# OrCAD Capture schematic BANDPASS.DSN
size A; title: Demo; rev: A; company: EMA Design Automation; note: EMA-12345678; note: 225 Tech Park Dr; note: Rochester, NY, 14623
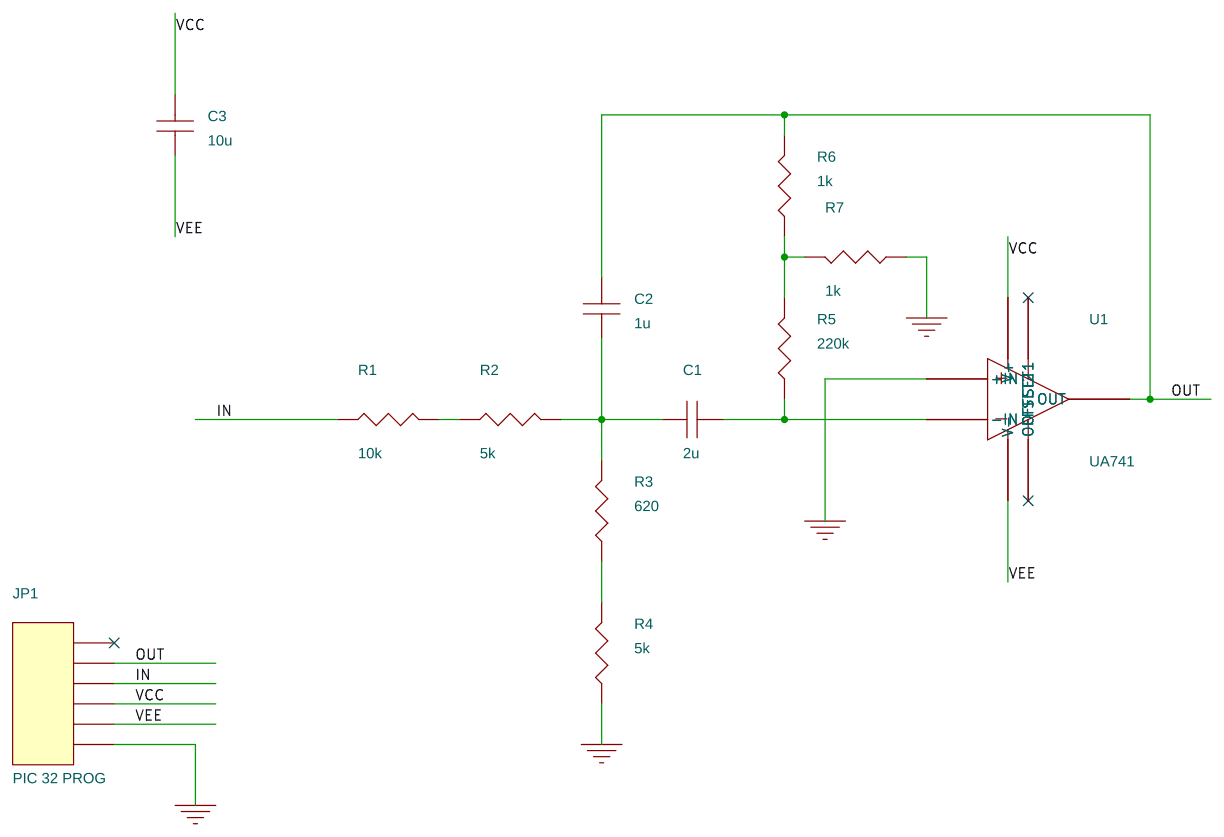
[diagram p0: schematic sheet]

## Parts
C1  2u  [0402-CAP]
C2  1u  [0402-CAP]
C3  10u  [0402-CAP]
JP1  PIC 32 PROG  [1x06_lock]
R1  10k  [0402-RES]
R2  5k  [0402-RES]
R3  620  [0402-RES]
R4  5k  [0402-RES]
R5  220k  [0402-RES]
R6  1k  [0402-RES]
R7  1k  [0402-RES]
U1  UA741  [SOIC8]

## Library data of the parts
C1-C3 = CAP_NP
JP1 = M06_LOCK: Manufacturer: TE Connectivity; Manufacturer_Part_Number: 640456-6; Part Number: A1923-ND; Vendor: DigiKey
R1-R7 = RESISTOR
U1 = UA741_1

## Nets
GND: JP1.1 R4.1 R7.1 U1.3(+IN)
VCC: C3.2 JP1.3 U1.7(V+)
VEE: C3.1 JP1.2 U1.4(V-)
IN: JP1.4 R1.1
OUT: C2.2 JP1.5 R6.2 U1.6(OUT)
N00185: R1.2 R2.1
N00342: R3.1 R4.2
N00346: C1.1 C2.1 R2.2 R3.2
N00400: C1.2 R5.1 U1.2(-IN)
N00573: R5.2 R6.1 R7.2

Not connected (* = marked no-connect by the designer): JP1 6*; U1 1(OFFSET1)* 5(OFFSET2)*
